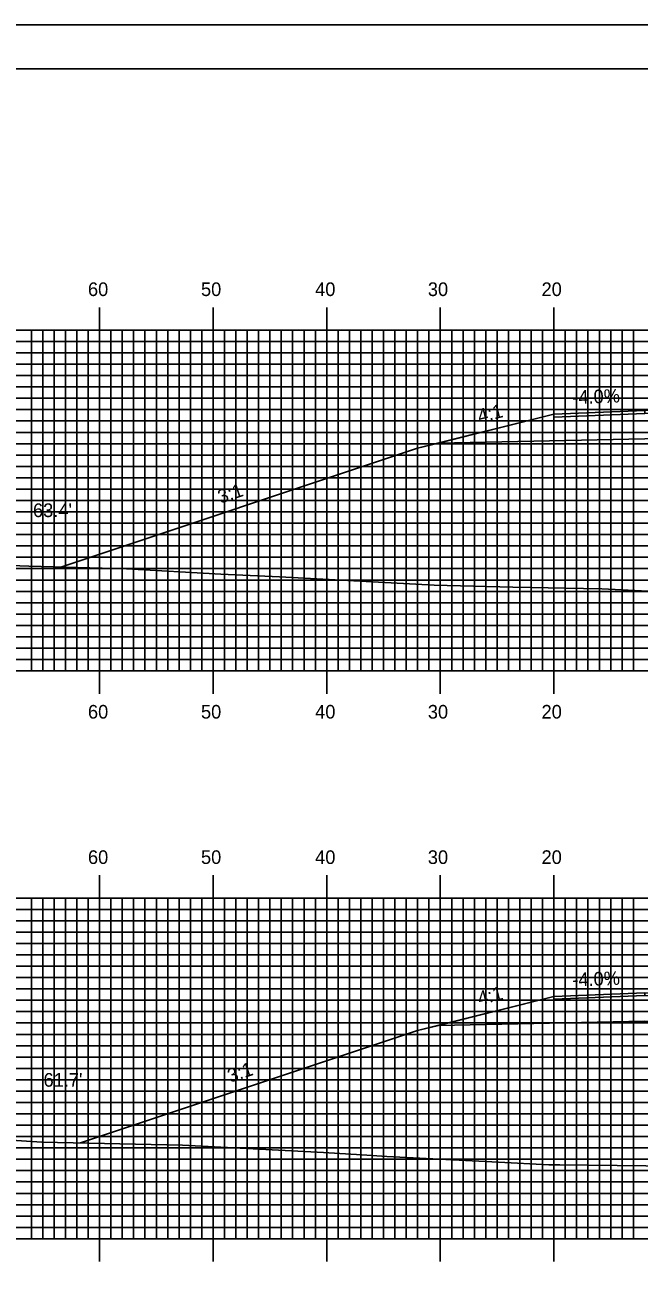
# Model space of a CAD drawing. Extents: x 1815309 to 1815652, y 442591 to 442811.
# Drawn here: x 1815408 to 1815462, y 442701.2 to 442810.5 of the extents above; entities that cross this region are included whole.
import ezdxf

# ---------------------------------------------------------------- set-up
doc = ezdxf.new("R2010")
doc.units = 0
for name, color, linetype in [('ANNOTATION', 7, 'Continuous'), ('BORDER', 7, 'Continuous'), ('D_Roadway_Centerline', 7, 'Continuous'), ('D_Roadway_Edge_Shoulder', 7, 'Continuous'), ('D_Roadway_SlopeLines', 7, 'Continuous'), ('D_Roadway_SubGrade', 7, 'Continuous'), ('D_Text_Standard', 7, 'Continuous'), ('H_V ANNOTATION', 7, 'Continuous'), ('MAJOR', 7, 'Continuous'), ('MINOR', 7, 'Continuous'), ('PLOT BOUNDARY', 7, 'Continuous'), ('S_Roadway_Centerline', 7, 'Continuous')]:
    doc.layers.add(name, color=color, linetype=linetype)

msp = doc.modelspace()

# ---------------------------------------------------------------- linework, layer by layer
at = {"layer": 'BORDER'}
msp.add_lwpolyline([(1815324.93, 442596.67), (1815644.93, 442596.67), (1815644.93, 442806.67), (1815324.93, 442806.67)], close=True, dxfattribs=at)
at = {"layer": 'D_Roadway_Centerline'}
for points in [[(1815411.13, 442762.8), (1815442.53, 442773.27), (1815444.36, 442773.73), (1815454.53, 442776.27), (1815462.53, 442776.59), (1815474.53, 442776.77), (1815486.53, 442776.53), (1815494.53, 442776.21), (1815504.71, 442773.67), (1815506.53, 442773.21), (1815545.26, 442760.3)], [(1815412.84, 442712.11), (1815442.53, 442722.01), (1815444.36, 442722.46), (1815454.53, 442725.01), (1815462.53, 442725.33), (1815474.53, 442725.27), (1815486.53, 442725.03), (1815494.53, 442724.71), (1815504.71, 442722.17), (1815506.53, 442721.71), (1815541.27, 442710.13)]]:
    msp.add_lwpolyline(points, dxfattribs=at)
at = {"layer": 'D_Roadway_Edge_Shoulder'}
for points in [[(1815462.53, 442776.59), (1815454.53, 442776.27), (1815454.53, 442776.02), (1815462.53, 442776.34)], [(1815462.53, 442725.33), (1815454.53, 442725.01), (1815454.53, 442724.76), (1815462.53, 442725.08)]]:
    msp.add_lwpolyline(points, close=True, dxfattribs=at)
at = {"layer": 'D_Roadway_SlopeLines'}
for points in [[(1815454.53, 442776.27), (1815442.53, 442773.27), (1815411.13, 442762.8)], [(1815454.53, 442725.01), (1815442.53, 442722.01), (1815412.84, 442712.11)]]:
    msp.add_lwpolyline(points, dxfattribs=at)
at = {"layer": 'D_Roadway_SubGrade'}
for points in [[(1815462.53, 442774.09), (1815444.36, 442773.73), (1815454.53, 442776.27), (1815454.53, 442776.02), (1815462.53, 442776.34), (1815474.53, 442776.52), (1815486.53, 442776.28), (1815494.53, 442775.96), (1815494.53, 442776.21), (1815504.71, 442773.67), (1815486.53, 442774.03), (1815474.53, 442774.27)], [(1815462.53, 442722.83), (1815444.36, 442722.46), (1815454.53, 442725.01), (1815454.53, 442724.76), (1815462.53, 442725.08), (1815474.53, 442725.02), (1815486.53, 442724.78), (1815494.53, 442724.46), (1815494.53, 442724.71), (1815504.71, 442722.17), (1815486.53, 442722.53), (1815474.53, 442722.77)]]:
    msp.add_lwpolyline(points, close=True, dxfattribs=at)
at = {"layer": 'MAJOR'}
for p, q in [((1815414.53, 442785.67), (1815414.53, 442783.67)), ((1815424.53, 442785.67), (1815424.53, 442783.67)), ((1815434.53, 442785.67), (1815434.53, 442783.67)), ((1815444.53, 442785.67), (1815444.53, 442783.67)), ((1815454.53, 442785.67), (1815454.53, 442783.67)), ((1815334.53, 442783.67), (1815614.53, 442783.67)), ((1815334.53, 442783.67), (1815614.53, 442783.67)), ((1815414.53, 442753.67), (1815414.53, 442783.67)), ((1815424.53, 442753.67), (1815424.53, 442783.67)), ((1815434.53, 442753.67), (1815434.53, 442783.67)), ((1815444.53, 442753.67), (1815444.53, 442783.67)), ((1815454.53, 442753.67), (1815454.53, 442783.67)), ((1815334.53, 442778.67), (1815614.53, 442778.67)), ((1815334.53, 442773.67), (1815614.53, 442773.67)), ((1815334.53, 442768.67), (1815614.53, 442768.67)), ((1815334.53, 442763.67), (1815614.53, 442763.67)), ((1815334.53, 442758.67), (1815614.53, 442758.67)), ((1815334.53, 442753.67), (1815614.53, 442753.67)), ((1815334.53, 442753.67), (1815614.53, 442753.67)), ((1815414.53, 442751.66), (1815414.53, 442753.67)), ((1815424.53, 442751.66), (1815424.53, 442753.67)), ((1815434.53, 442751.66), (1815434.53, 442753.67)), ((1815444.53, 442751.66), (1815444.53, 442753.67)), ((1815454.53, 442751.66), (1815454.53, 442753.67)), ((1815414.53, 442735.67), (1815414.53, 442733.67)), ((1815424.53, 442735.67), (1815424.53, 442733.67)), ((1815434.53, 442735.67), (1815434.53, 442733.67)), ((1815444.53, 442735.67), (1815444.53, 442733.67)), ((1815454.53, 442735.67), (1815454.53, 442733.67)), ((1815334.53, 442733.67), (1815614.53, 442733.67)), ((1815334.53, 442733.67), (1815614.53, 442733.67)), ((1815414.53, 442703.67), (1815414.53, 442733.67)), ((1815424.53, 442703.67), (1815424.53, 442733.67)), ((1815434.53, 442703.67), (1815434.53, 442733.67)), ((1815444.53, 442703.67), (1815444.53, 442733.67)), ((1815454.53, 442703.67), (1815454.53, 442733.67)), ((1815334.53, 442728.67), (1815614.53, 442728.67)), ((1815334.53, 442723.67), (1815614.53, 442723.67)), ((1815334.53, 442718.67), (1815614.53, 442718.67)), ((1815334.53, 442713.67), (1815614.53, 442713.67)), ((1815334.53, 442708.67), (1815614.53, 442708.67)), ((1815334.53, 442703.67), (1815614.53, 442703.67)), ((1815334.53, 442703.67), (1815614.53, 442703.67)), ((1815414.53, 442701.66), (1815414.53, 442703.67)), ((1815424.53, 442701.66), (1815424.53, 442703.67)), ((1815434.53, 442701.66), (1815434.53, 442703.67)), ((1815444.53, 442701.66), (1815444.53, 442703.67)), ((1815454.53, 442701.66), (1815454.53, 442703.67))]:
    msp.add_line(p, q, dxfattribs=at)
at = {"layer": 'MINOR'}
for p, q in [((1815408.53, 442753.67), (1815408.53, 442783.67)), ((1815409.53, 442753.67), (1815409.53, 442783.67)), ((1815410.53, 442753.67), (1815410.53, 442783.67)), ((1815411.53, 442753.67), (1815411.53, 442783.67)), ((1815412.53, 442753.67), (1815412.53, 442783.67)), ((1815413.53, 442753.67), (1815413.53, 442783.67)), ((1815415.53, 442753.67), (1815415.53, 442783.67)), ((1815416.53, 442753.67), (1815416.53, 442783.67)), ((1815417.53, 442753.67), (1815417.53, 442783.67)), ((1815418.53, 442753.67), (1815418.53, 442783.67)), ((1815419.53, 442753.67), (1815419.53, 442783.67)), ((1815420.53, 442753.67), (1815420.53, 442783.67)), ((1815421.53, 442753.67), (1815421.53, 442783.67)), ((1815422.53, 442753.67), (1815422.53, 442783.67)), ((1815423.53, 442753.67), (1815423.53, 442783.67)), ((1815425.53, 442753.67), (1815425.53, 442783.67)), ((1815426.53, 442753.67), (1815426.53, 442783.67)), ((1815427.53, 442753.67), (1815427.53, 442783.67)), ((1815428.53, 442753.67), (1815428.53, 442783.67)), ((1815429.53, 442753.67), (1815429.53, 442783.67)), ((1815430.53, 442753.67), (1815430.53, 442783.67)), ((1815431.53, 442753.67), (1815431.53, 442783.67)), ((1815432.53, 442753.67), (1815432.53, 442783.67)), ((1815433.53, 442753.67), (1815433.53, 442783.67)), ((1815435.53, 442753.67), (1815435.53, 442783.67)), ((1815436.53, 442753.67), (1815436.53, 442783.67)), ((1815437.53, 442753.67), (1815437.53, 442783.67)), ((1815438.53, 442753.67), (1815438.53, 442783.67)), ((1815439.53, 442753.67), (1815439.53, 442783.67)), ((1815440.53, 442753.67), (1815440.53, 442783.67)), ((1815441.53, 442753.67), (1815441.53, 442783.67)), ((1815442.53, 442753.67), (1815442.53, 442783.67)), ((1815443.53, 442753.67), (1815443.53, 442783.67)), ((1815445.53, 442753.67), (1815445.53, 442783.67)), ((1815446.53, 442753.67), (1815446.53, 442783.67)), ((1815447.53, 442753.67), (1815447.53, 442783.67)), ((1815448.53, 442753.67), (1815448.53, 442783.67)), ((1815449.53, 442753.67), (1815449.53, 442783.67)), ((1815450.53, 442753.67), (1815450.53, 442783.67)), ((1815451.53, 442753.67), (1815451.53, 442783.67)), ((1815452.53, 442753.67), (1815452.53, 442783.67)), ((1815453.53, 442753.67), (1815453.53, 442783.67)), ((1815455.53, 442753.67), (1815455.53, 442783.67)), ((1815456.53, 442753.67), (1815456.53, 442783.67)), ((1815457.53, 442753.67), (1815457.53, 442783.67)), ((1815458.53, 442753.67), (1815458.53, 442783.67)), ((1815459.53, 442753.67), (1815459.53, 442783.67)), ((1815460.53, 442753.67), (1815460.53, 442783.67)), ((1815461.53, 442753.67), (1815461.53, 442783.67)), ((1815334.53, 442782.67), (1815614.53, 442782.67)), ((1815334.53, 442781.67), (1815614.53, 442781.67)), ((1815334.53, 442780.67), (1815614.53, 442780.67)), ((1815334.53, 442779.67), (1815614.53, 442779.67)), ((1815334.53, 442777.67), (1815614.53, 442777.67)), ((1815334.53, 442776.67), (1815614.53, 442776.67)), ((1815334.53, 442775.67), (1815614.53, 442775.67)), ((1815334.53, 442774.67), (1815614.53, 442774.67)), ((1815334.53, 442772.67), (1815614.53, 442772.67)), ((1815334.53, 442771.67), (1815614.53, 442771.67)), ((1815334.53, 442770.67), (1815614.53, 442770.67)), ((1815334.53, 442769.67), (1815614.53, 442769.67)), ((1815334.53, 442767.67), (1815614.53, 442767.67)), ((1815334.53, 442766.67), (1815614.53, 442766.67)), ((1815334.53, 442765.67), (1815614.53, 442765.67)), ((1815334.53, 442764.67), (1815614.53, 442764.67)), ((1815334.53, 442762.67), (1815614.53, 442762.67)), ((1815334.53, 442761.67), (1815614.53, 442761.67)), ((1815334.53, 442760.67), (1815614.53, 442760.67)), ((1815334.53, 442759.67), (1815614.53, 442759.67)), ((1815334.53, 442757.67), (1815614.53, 442757.67)), ((1815334.53, 442756.67), (1815614.53, 442756.67)), ((1815334.53, 442755.67), (1815614.53, 442755.67)), ((1815334.53, 442754.67), (1815614.53, 442754.67)), ((1815408.53, 442703.67), (1815408.53, 442733.67)), ((1815409.53, 442703.67), (1815409.53, 442733.67)), ((1815410.53, 442703.67), (1815410.53, 442733.67)), ((1815411.53, 442703.67), (1815411.53, 442733.67)), ((1815412.53, 442703.67), (1815412.53, 442733.67)), ((1815413.53, 442703.67), (1815413.53, 442733.67)), ((1815415.53, 442703.67), (1815415.53, 442733.67)), ((1815416.53, 442703.67), (1815416.53, 442733.67)), ((1815417.53, 442703.67), (1815417.53, 442733.67)), ((1815418.53, 442703.67), (1815418.53, 442733.67)), ((1815419.53, 442703.67), (1815419.53, 442733.67)), ((1815420.53, 442703.67), (1815420.53, 442733.67)), ((1815421.53, 442703.67), (1815421.53, 442733.67)), ((1815422.53, 442703.67), (1815422.53, 442733.67)), ((1815423.53, 442703.67), (1815423.53, 442733.67)), ((1815425.53, 442703.67), (1815425.53, 442733.67)), ((1815426.53, 442703.67), (1815426.53, 442733.67)), ((1815427.53, 442703.67), (1815427.53, 442733.67)), ((1815428.53, 442703.67), (1815428.53, 442733.67)), ((1815429.53, 442703.67), (1815429.53, 442733.67)), ((1815430.53, 442703.67), (1815430.53, 442733.67)), ((1815431.53, 442703.67), (1815431.53, 442733.67)), ((1815432.53, 442703.67), (1815432.53, 442733.67)), ((1815433.53, 442703.67), (1815433.53, 442733.67)), ((1815435.53, 442703.67), (1815435.53, 442733.67)), ((1815436.53, 442703.67), (1815436.53, 442733.67)), ((1815437.53, 442703.67), (1815437.53, 442733.67)), ((1815438.53, 442703.67), (1815438.53, 442733.67)), ((1815439.53, 442703.67), (1815439.53, 442733.67)), ((1815440.53, 442703.67), (1815440.53, 442733.67)), ((1815441.53, 442703.67), (1815441.53, 442733.67)), ((1815442.53, 442703.67), (1815442.53, 442733.67)), ((1815443.53, 442703.67), (1815443.53, 442733.67)), ((1815445.53, 442703.67), (1815445.53, 442733.67)), ((1815446.53, 442703.67), (1815446.53, 442733.67)), ((1815447.53, 442703.67), (1815447.53, 442733.67)), ((1815448.53, 442703.67), (1815448.53, 442733.67)), ((1815449.53, 442703.67), (1815449.53, 442733.67)), ((1815450.53, 442703.67), (1815450.53, 442733.67)), ((1815451.53, 442703.67), (1815451.53, 442733.67)), ((1815452.53, 442703.67), (1815452.53, 442733.67)), ((1815453.53, 442703.67), (1815453.53, 442733.67)), ((1815455.53, 442703.67), (1815455.53, 442733.67)), ((1815456.53, 442703.67), (1815456.53, 442733.67)), ((1815457.53, 442703.67), (1815457.53, 442733.67)), ((1815458.53, 442703.67), (1815458.53, 442733.67)), ((1815459.53, 442703.67), (1815459.53, 442733.67)), ((1815460.53, 442703.67), (1815460.53, 442733.67)), ((1815461.53, 442703.67), (1815461.53, 442733.67)), ((1815334.53, 442732.67), (1815614.53, 442732.67)), ((1815334.53, 442731.67), (1815614.53, 442731.67)), ((1815334.53, 442730.67), (1815614.53, 442730.67)), ((1815334.53, 442729.67), (1815614.53, 442729.67)), ((1815334.53, 442727.67), (1815614.53, 442727.67)), ((1815334.53, 442726.67), (1815614.53, 442726.67)), ((1815334.53, 442725.67), (1815614.53, 442725.67)), ((1815334.53, 442724.67), (1815614.53, 442724.67)), ((1815334.53, 442722.67), (1815614.53, 442722.67)), ((1815334.53, 442721.67), (1815614.53, 442721.67)), ((1815334.53, 442720.67), (1815614.53, 442720.67)), ((1815334.53, 442719.67), (1815614.53, 442719.67)), ((1815334.53, 442717.67), (1815614.53, 442717.67)), ((1815334.53, 442716.67), (1815614.53, 442716.67)), ((1815334.53, 442715.67), (1815614.53, 442715.67)), ((1815334.53, 442714.67), (1815614.53, 442714.67)), ((1815334.53, 442712.67), (1815614.53, 442712.67)), ((1815334.53, 442711.67), (1815614.53, 442711.67)), ((1815334.53, 442710.67), (1815614.53, 442710.67)), ((1815334.53, 442709.67), (1815614.53, 442709.67)), ((1815334.53, 442707.67), (1815614.53, 442707.67)), ((1815334.53, 442706.67), (1815614.53, 442706.67)), ((1815334.53, 442705.67), (1815614.53, 442705.67)), ((1815334.53, 442704.67), (1815614.53, 442704.67))]:
    msp.add_line(p, q, dxfattribs=at)
at = {"layer": 'PLOT BOUNDARY'}
msp.add_lwpolyline([(1815308.75, 442590.55), (1815648.75, 442590.55), (1815648.75, 442810.55), (1815308.75, 442810.55)], close=True, dxfattribs=at)
at = {"layer": 'S_Roadway_Centerline'}
for points in [[(1815393.38, 442763.44), (1815408.3, 442762.88), (1815416.89, 442762.65), (1815425.21, 442762.19), (1815430.38, 442761.94), (1815442.38, 442761.3), (1815443.99, 442761.22), (1815450.92, 442761.05), (1815457.13, 442760.91), (1815458.74, 442760.88), (1815469.81, 442760.34), (1815475.74, 442760.17), (1815483.72, 442760.39), (1815492.68, 442760.29), (1815496.59, 442760.17), (1815510.25, 442759.81), (1815526.98, 442760.01), (1815537.6, 442760.33)], [(1815404.5, 442712.5), (1815409.44, 442712.19), (1815421.82, 442711.9), (1815434.24, 442711.27), (1815437.61, 442711.07), (1815439.81, 442710.91), (1815449.64, 442710.43), (1815454.09, 442710.17), (1815455.05, 442710.17), (1815467.67, 442710.02), (1815471.06, 442709.93), (1815481.55, 442709.82), (1815489.45, 442709.66), (1815493.35, 442709.88), (1815495.31, 442709.91), (1815506.57, 442709.97), (1815517.69, 442709.81), (1815523.52, 442709.73), (1815525.6, 442709.76), (1815539.97, 442710.15)]]:
    msp.add_lwpolyline(points, dxfattribs=at)

# ---------------------------------------------------------------- texts
at = {"layer": 'ANNOTATION'}
for s, rotation, p in [('-4.0%', 2.2906, (1815456.17, 442777.14)), ('4:1', 14.0362, (1815447.98, 442775.49)), ('3:1', 18.4348, (1815425.17, 442768.39)), ('-4.0%', 2.2906, (1815456.17, 442725.87)), ('4:1', 14.0362, (1815447.98, 442724.23)), ('3:1', 18.4348, (1815426.03, 442717.41))]:
    msp.add_text(s, height=1.2, rotation=rotation, dxfattribs=at).set_placement(p)
at = {"layer": 'D_Text_Standard'}
for s, p in [("63.4'", (1815408.67, 442767.21)), ("61.7'", (1815409.6, 442717.06))]:
    msp.add_text(s, height=1.2, dxfattribs=at).set_placement(p)
at = {"layer": 'H_V ANNOTATION'}
for s, p in [('60', (1815413.51, 442786.67)), ('50', (1815423.46, 442786.67)), ('40', (1815433.51, 442786.67)), ('30', (1815443.43, 442786.67)), ('20', (1815453.44, 442786.67)), ('60', (1815413.51, 442749.47)), ('50', (1815423.46, 442749.47)), ('40', (1815433.51, 442749.47)), ('30', (1815443.43, 442749.47)), ('20', (1815453.44, 442749.47)), ('60', (1815413.51, 442736.67)), ('50', (1815423.46, 442736.67)), ('40', (1815433.51, 442736.67)), ('30', (1815443.43, 442736.67)), ('20', (1815453.44, 442736.67))]:
    msp.add_text(s, height=1.2, dxfattribs=at).set_placement(p)

doc.saveas('drawing.dxf')
